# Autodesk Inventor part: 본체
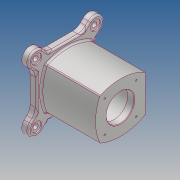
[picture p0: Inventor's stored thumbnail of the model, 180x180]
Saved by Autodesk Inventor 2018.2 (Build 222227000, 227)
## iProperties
Created: 2022-01
Part Number: 본체
Material: 알루미늄 6061
Document SubType Name: Modeling
Designer: woori
Density: 2.7 g/cm^3
Appearance: 알루미늄 - 평지
Mass: 1225.02 g
Surface Area: 908.487 cm^2
Volume: 453.711 cm^3
Author: woori
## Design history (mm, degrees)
sketch "스케치1"
  geometry: L1 (-53, 53)-(53, 53); L2 (53, 53)-(53, -53); L3 (53, -53)-(-53, -53); L4 (-53, -53)-(-53, 53); L5 (-53, 53)-(53, -53); L6 (53, 53)-(-53, -53); L7 (63.607, -42.393)-(53, -31.787); L8 (31.787, -53)-(42.393, -63.607); L9 (-31.787, -53)-(-42.393, -63.607); L10 (-53, -31.787)-(-63.607, -42.393); L11 (-63.607, 42.393)-(-53, 31.787); L12 (-31.787, 53)-(-42.393, 63.607); L13 (63.607, 42.393)-(53, 31.787); L14 (42.393, 63.607)-(31.787, 53); A1 r 15 centre (53, 53) between (63.607, 42.393) and (42.393, 63.607); A2 r 15 centre (53, -53) between (42.393, -63.607) and (63.607, -42.393); A3 r 15 centre (-53, -53) between (-63.607, -42.393) and (-42.393, -63.607); A4 r 15 centre (-53, 53) between (-42.393, 63.607) and (-63.607, 42.393); 9 further points
  constraints: 28 end point, 16 point on line, 9 parallel, 8 point on circle, 5 tangent, 4 centre point, 4 coincident, 2 midpoint, 1 horizontal, 1 perpendicular, 3 other
  dimensions: "d0" = 106 distance between parallel lines of L3 L1; "d1" = 106 distance of L2.end L3.end; "d3" = 30 diameter of A1; "d4" = 30 diameter of A2; "d5" = 30 diameter of A3; "d6" = 30 diameter of A4
extrude "돌출1" new body sketch "스케치1" distance "d7" = 12; taper "d8" = 0 deg
node "작업 평면1"
sketch "스케치7"
  geometry: L1 (-45, 45)-(45, 45); L2 (45, 45)-(45, -45); L3 (45, -45)-(-45, -45); L4 (-45, -45)-(-45, 45); L5 (-45, 45)-(45, -45); L6 (45, 45)-(-45, -45); A1 r 90 centre (45, 0) between (-32.942, 45) and (-32.942, -45); A2 r 90 centre (0, -45) between (45, 32.942) and (-45, 32.942); A3 r 90 centre (0, 45) between (-45, -32.942) and (45, -32.942); 1 further point
  constraints: 12 end point, 8 point on circle, 6 point on line, 5 midpoint, 3 centre point, 2 parallel, 1 horizontal, 1 perpendicular, 1 tangent
  dimensions: "d30" = 90 distance of L2.end L3.end; "d31" = 90 distance of L1.end L2.end; "d32" = 180 diameter of A2
extrude "돌출5" join sketch "스케치7" distance "d33" = 98; taper "d34" = 0 deg
sketch "스케치8"
  geometry: L1 (-32.942, 45)-(32.942, 45) reference; L2 (129.574, -96.698)-(-129.574, -96.698); L3 (-129.574, -96.698)-(-129.574, 186.698); L4 (-129.574, 186.698)-(129.574, 186.698); L5 (129.574, 186.698)-(129.574, -96.698); L6 (129.574, -96.698)-(-129.574, 186.698); L7 (-129.574, -96.698)-(129.574, 186.698); C1 r 90 at (0, 45); 1 further point
  constraints: 12 end point, 3 midpoint, 2 parallel, 1 centre point, 1 horizontal, 1 perpendicular
  dimensions: "d35" = 180 diameter of C1; "d36" = 283.39565 distance between parallel lines of L2 L4; "d37" = 259.14864 distance between parallel lines of L3 L5
extrude "돌출6" cut sketch "스케치8" distance "d38" = 98; taper "d39" = 0 deg
sketch "스케치9"
  geometry: L1 (110, -37.029)-(110, 45) reference; L2 (110, 0)-(110, 25); L3 (110, 25)-(98, 25); L4 (12, 45)-(12, -37.029) reference; L5 (110, 0)-(0, 0); L6 (98, 25)-(98, 37); L7 (98, 37)-(12, 37); L8 (12, 37)-(12, 25); L9 (0, 25)-(0, 0); L10 (0, 31.787)-(0, -31.787) reference; L11 (12, 25)-(0, 25); 2 further points
  constraints: 16 end point, 3 point on line, 2 horizontal, 2 perpendicular, 1 collinear, 1 vertical
  dimensions: "d40" = 25 distance of L2.start L2.end; "d47" = 12 distance of L2.end L3.end; "d48" = 37 distance between parallel lines of L5 L7; "d49" = 86 distance of L6.end L7.end; "d50" = 25 distance between parallel lines of L5 L11
revolve "회전2" sketch "스케치9" stored, may be unused: angle "d51" = 90 deg
sketch "스케치10"
  geometry: L1 (0, 65.885)-(0, 0) reference; L2 (-110, 64.729)-(-110, 1.155) reference; C1 r 20 at (-49, 32.942); 4 further points
  constraints: 1 centre point, 1 horizontal alignment, 1 midpoint
  dimensions: "d52" = 40 diameter of C1; "d53" = 61 distance from line of C1.centre L2
extrude "돌출7" join sketch "스케치10" distance "d54" = 10; taper "d55" = 0 deg
feature "면 기울기1" dims angle "d56" = 10 deg
sketch "스케치11"
  geometry: C1 r 20 at (0, 0) reference; C2 r 12 at (0, 0); 1 further point
  constraints: 1 centre point, 1 coincident
  dimensions: "d58" = 24 diameter of C2
extrude "돌출8" cut sketch "스케치11" distance "d59" = 30; taper "d60" = 0 deg
node "작업 평면2"
sketch "스케치12"
  geometry: C1 r 12 at (0, 0) reference; C2 r 15 at (0, 0); 1 further point
  constraints: 1 centre point, 1 coincident
  dimensions: "d62" = 30 diameter of C2
extrude "돌출9" cut sketch "스케치12" distance "d63" = 30; taper "d64" = 0 deg
sketch "스케치13" dims "d65" = 80
  geometry: L1 (53, -53)-(-53, 53); A1 r 15 centre (53, -53) between (42.393, -63.607) and (63.607, -42.393) reference; A2 r 15 centre (-53, 53) between (-42.393, 63.607) and (-63.607, 42.393) reference; A3 r 15 centre (-53, -53) between (-63.607, -42.393) and (-42.393, -63.607) reference; A4 r 15 centre (53, 53) between (63.607, 42.393) and (42.393, 63.607) reference; 11 further points
  constraints: 2 end point, 1 coincident, 1 point on line, 3 other
hole "구멍1" sketch "스케치13" at (-28.284, 28.284) diameter "d66" = 3.242; stored, may be unused: countersink angle "d70" = 90 deg, drill point angle "d72" = 118 deg; dims "d67" = 9, "d68" = 4, "d69" = 2, "d71" = 11
fillet "모깎기1" dims "d76" = 20
sketch "스케치14" dims "d77" = 80
  geometry: L1 (53, 53)-(-53, -53); A1 r 15 centre (53, 53) between (63.607, 42.393) and (42.393, 63.607) reference; A2 r 15 centre (-53, -53) between (-63.607, -42.393) and (-42.393, -63.607) reference; 7 further points
  constraints: 2 end point, 1 coincident, 1 point on line, 3 other
hole "구멍2" sketch "스케치14" at (28.284, 28.284) diameter "d78" = 3.242; stored, may be unused: countersink angle "d82" = 90 deg, drill point angle "d84" = 118 deg; dims "d79" = 9, "d80" = 4, "d81" = 2, "d83" = 11
sketch "스케치16" dims "d89" = 150
  geometry: L1 (53, 53)-(-53, -53); A1 r 15 centre (53, 53) between (63.607, 42.393) and (42.393, 63.607) reference; A2 r 15 centre (-53, -53) between (-63.607, -42.393) and (-42.393, -63.607) reference; 7 further points
  constraints: 2 end point, 1 coincident, 1 point on line, 3 other
hole "구멍3" sketch "스케치16" at (53.033, 53.033) diameter "d90" = 9; stored, may be unused: countersink angle "d94" = 90 deg, drill point angle "d96" = 118 deg; dims "d91" = 9, "d92" = 18, "d93" = 2, "d95" = 11
node "작업 평면3"
sketch "스케치17"
  geometry: L1 (-94.777, 29.147)-(-27.223, 29.147); L2 (-27.223, 29.147)-(-27.223, -29.147); L3 (-27.223, -29.147)-(-94.777, -29.147); L4 (-94.777, -29.147)-(-94.777, 29.147); L5 (-27.223, -29.147)-(-94.777, -29.147); L6 (-94.777, -29.147)-(-94.777, 29.147); L7 (-94.777, 29.147)-(-27.223, 29.147); L8 (-27.223, 29.147)-(-27.223, -29.147); L9 (-27.223, -29.147)-(-94.777, 29.147); L10 (-94.777, -29.147)-(-27.223, 29.147); L11 (-41, 55)-(-81, 55) reference; L12 (0, 68)-(0, 63.607) reference; 4 further points
  constraints: 12 end point, 2 coincident, 2 midpoint, 2 parallel, 1 horizontal, 1 perpendicular, 2 other
  dimensions: "d101" = 55 distance from line of point (-61, 0) L11; "d102" = 61 distance from line of L12 point (-61, 0)
extrude "돌출10" join sketch "스케치17" stored distance "d103" = 30; taper "d104" = 0 deg
fillet "모깎기2" dims "d105" = 1
fillet "모깎기3" dims "d106" = 3
fillet "모깎기4" dims "d107" = 3
fillet "모깎기5" dims "d108" = 3
sketch "스케치18"
  geometry: 1 further point
fillet "모깎기6" dims "d109" = 20
node "솔리드1"
pattern_circular "원형 패턴1" dims angle "d74" = 360 deg
pattern_circular "원형 패턴2" dims angle "d86" = 360 deg
pattern_circular "원형 패턴3" dims angle "d98" = 360 deg
other parameters: "d61" = -13, "d100" = -45.5
